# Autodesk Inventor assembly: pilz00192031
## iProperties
Shininess: 64.0
Length Units: 11269
Angle Units: 11279
Time Units: 11290
Mass Units: 11283
Length Display Precision: 2
Angle Display Precision: 2
Compacted: True
Created: 2004-04
Part Number: pilz00192031
Document SubType Name: Assembly
Cost Center: 0 kg
Authority: 0 mm^3
Designer: Administrator
Manufacturer: Standard
Standards Organization: Custom
Project: LED-Gehäuse
Density: 0.0
Volumn: 0.0
Area: 0.0
PropertySet Name: Model Information
Control State: 0
Master: False
Checked Out: False
ArtNr: T00192031
SaveDate: 2003-11-11
SaveTime: 13:45
TotalMass: 0 kg
TotalVolume: 0 mm^3
Farbe: RAL 7042 matt
Beschichtungsart: beschichtet
GesGewicht: 0,0kg
Zeichnungsnummer: pilz001920
Author: Ch.Steinmetz
Title: Türblech
Subject: für 1500x1800 Typ A1R
